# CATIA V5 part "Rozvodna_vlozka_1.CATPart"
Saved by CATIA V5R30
Part number: Rozvodna_vlozka_1
Definition: EH 6304_20_12
Nomenclature: EH 6304_20_12
Source: Unknown
Description: PART--DESC
Bounding box of the stored display mesh (mm): x -135.2 to -79.5, y -11 to 11, z 56.71 to 78.69
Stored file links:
  E:\Bakalarka\Model\Forma_v7\Rozvodna_vlozka_1.CATPart
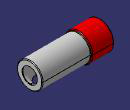
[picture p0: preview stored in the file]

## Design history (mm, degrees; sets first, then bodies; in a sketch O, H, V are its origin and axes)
Body1 "MANIFOLD_SOLID_BREP #3746" (main body)
  Solid1: solid without history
